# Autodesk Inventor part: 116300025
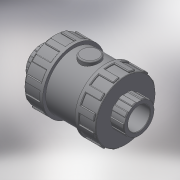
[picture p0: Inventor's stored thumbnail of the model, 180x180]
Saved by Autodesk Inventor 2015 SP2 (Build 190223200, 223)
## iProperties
Created: 2017-11
Part Number: 116300025
Material: Generic
Description: PLASSON AIR RELEASE VALVE CEM PVC 25
Document SubType Name: Modeling
Designer: KIM
Density: 1 g/cm^3
Appearance: Default
Author: KIM
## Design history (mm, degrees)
derived "116300 - 116900.ipt"
feature "Solid1::116300 - 116900.ipt"
tag "TaggingFeature1"
body "Solid1"
other parameters: "d0" = 89, "d1" = 25, "d2" = 55, "d3" = 19, "d5" = 13.3, "d7" = 35, "d8" = 49.5, "d13" = 0.75, "d23" = 19, "d24" = 52.8, "d25" = 0.5, "d26" = 0.75, "d27" = 8.25, "d28" = 4.125, "d29" = 14.25, "d30" = 0, "d35" = 0.75, "d39" = 27.5, "d45" = 360 deg, "d47" = 0.5, "d50" = 27.5, "d51" = 16.5, "d53" = 0, "d54" = 1.1, "d55" = 5, "d56" = 2.5, "d58" = 0, "d59" = 0.75, "d61" = 360 deg, "d_" = 25, "l_" = 19, "H_" = 89, "K_" = 55
